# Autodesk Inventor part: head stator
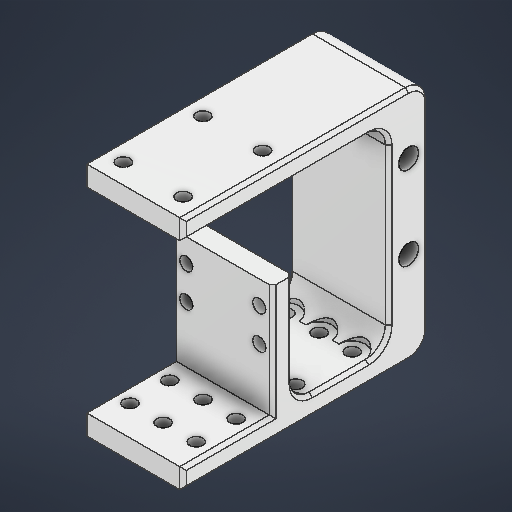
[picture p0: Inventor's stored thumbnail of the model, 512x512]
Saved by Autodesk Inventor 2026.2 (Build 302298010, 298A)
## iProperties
Created: 2026-04
Part Number: head stator
Material: ABS 플라스틱
Document SubType Name: Modeling
Designer: work
Density: 1.06 g/cm^3
Appearance: 매끄러움 - 흰색
Author: work
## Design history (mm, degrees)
sketch "스케치1"
  geometry: L1 (-12.5, 25)-(12.5, 25); L2 (12.5, 25)-(12.5, -25); L3 (12.5, -25)-(-12.5, -25); L4 (-12.5, -25)-(-12.5, 25); L5 (-12.5, 25)-(12.5, -25); L6 (12.5, 25)-(-12.5, -25); L7 (-24.5, 34)-(-0.5, 34); L8 (-0.5, 34)-(-0.5, 16); L9 (-0.5, 16)-(-24.5, 16); L10 (-24.5, 16)-(-24.5, 34); L11 (-24.5, 34)-(-0.5, 16); L12 (-0.5, 34)-(-24.5, 16); L13 (-18.5, -31)-(18.5, -31); L14 (18.5, -31)-(18.5, -19); L15 (18.5, -19)-(-18.5, -19); L16 (-18.5, -19)-(-18.5, -31); L17 (-18.5, -31)-(18.5, -19); L18 (18.5, -31)-(-18.5, -19); L19 (12.5, 25)-(24.5, 25); L20 (24.5, 43)-(30.5, 43); L21 (30.5, 43)-(30.5, -31); L22 (30.5, -31)-(24.5, -31); L23 (24.5, -31)-(24.5, 43); L24 (18.5, -19)-(24.5, -19); L25 (18.5, -31)-(24.5, -31); L26 (-18.5, 10)-(-24.5, 10); L27 (-24.5, 10)-(-24.5, -31); L28 (-24.5, -31)-(-18.5, -31); L29 (-18.5, -31)-(-18.5, 10); L30 (30.5, 37)-(24.5, 37); L31 (24.5, 37)-(24.5, 13); L32 (24.5, 13)-(30.5, 13); L33 (30.5, 13)-(30.5, 37); L34 (-6.5, 16)-(-18.5, 16); L35 (-18.5, 16)-(-18.5, 10); L36 (-18.5, 10)-(-6.5, 10); L37 (-6.5, 10)-(-6.5, 16); L38 (-0.5, 16)-(-24.5, 16); L39 (-24.5, 16)-(-24.5, 10); L40 (-24.5, 10)-(-0.5, 10); L41 (-0.5, 10)-(-0.5, 16); L42 (-18.5, -19)-(-34.5, -19); L43 (-34.5, -19)-(-34.5, -31); L44 (-34.5, -31)-(-18.5, -31); L45 (-18.5, -31)-(-18.5, -19); L46 (-34.5, -31)-(-40.5, -31); L47 (-40.5, -31)-(-40.5, 16); L48 (-40.5, 16)-(-34.5, 16); L49 (-34.5, 16)-(-34.5, -31); L50 (-34.5, 10)-(-24.5, 10); L51 (-24.5, 10)-(-24.5, 16); L52 (-24.5, 16)-(-34.5, 16); L53 (-34.5, 16)-(-34.5, 10); C1 r 4 at (12.5, 25); C2 r 3 at (12.5, -25); C3 r 3 at (-12.5, -25); 17 further points
  constraints: 106 end point, 23 parallel, 17 midpoint, 13 horizontal, 11 perpendicular, 5 point on line, 3 centre point, 3 coincident
  dimensions: "d0" = 25 distance of L2.end L3.end; "d1" = 50 distance of L1.end L2.end; "d2" = 8 diameter of C1; "d3" = 24 distance of L8.end L9.end; "d4" = 18 distance of L7.end L8.end; "d5" = 6 diameter of C2; "d6" = 6 diameter of C3; "d7" = 6 distance from line of L2.end L14; "d8" = 6 distance from line of L15 L2.end; "d9" = 12 distance of L19.end L19.start; "d11" = 24 distance from line of point (27.5, 13) L30; "d13" = 6 distance between parallel lines of L23 L21; "d14" = 6 distance between parallel lines of L30 L20; "d15" = 6 distance between parallel lines of L29 L27; "d17" = 6 distance of L34.end L35.end; "d18" = 12 distance from line of point (-18.5, 13) L37; "d19" = 6 distance between parallel lines of L39 L35; "d41" = 6 distance between parallel lines of L47 L49; "d42" = 10 distance between parallel lines of L53 L39
extrude "돌출1" new body sketch "스케치1" distance "d20" = 30; taper "d21" = 0 deg
sketch "스케치2"
  geometry: L1 (0, 74)-(0, 0) reference; L2 (0, 0)-(30, 0) reference; L3 (30, 74)-(30, 0) reference; L4 (0, 74)-(30, 74) reference; L5 (15, 0)-(15, 74); L6 (0, 37)-(30, 37); L7 (24, 30)-(6, 30); L8 (6, 30)-(6, 6); L9 (6, 6)-(24, 6); L10 (24, 6)-(24, 30); L11 (24, 30)-(6, 6); L12 (6, 30)-(24, 6); C1 r 2 at (6, 6); C2 r 2 at (24, 6); C3 r 2 at (24, 30); C4 r 2 at (6, 30); 2 further points
  constraints: 16 end point, 6 midpoint, 4 centre point, 4 coincident, 2 parallel, 1 horizontal, 1 perpendicular, 1 point on line
  dimensions: "d22" = 6 distance between parallel lines of L2 L9; "d23" = 24 distance of L7.end L8.end; "d24" = 18 distance of L8.end L9.end; "d25" = 4 diameter of C1; "d26" = 4 diameter of C2; "d27" = 4 diameter of C3; "d28" = 4 diameter of C4
extrude "돌출2" cut sketch "스케치2" stored distance "d29" = 36; taper "d30" = 0 deg
fillet "모깎기1" dims "d31" = 6
sketch "스케치4"
  geometry: L1 (30, 31)-(30, 25) reference; L2 (0, 31)-(0, 25) reference; L3 (0, 28)-(30, 28); L4 (26, 23)-(4, 23); L5 (4, 23)-(4, 33); L6 (4, 33)-(26, 33); L7 (26, 33)-(26, 23); L8 (26, 23)-(4, 33); L9 (4, 23)-(26, 33); C1 r 2 at (4, 23); C2 r 2 at (4, 33); C3 r 2 at (26, 33); C4 r 2 at (26, 23); 2 further points
  constraints: 14 end point, 5 midpoint, 4 centre point, 4 coincident, 2 parallel, 1 horizontal, 1 perpendicular
  dimensions: "d44" = 10 distance of L4.end L5.end; "d45" = 4 distance between parallel lines of L2 L5; "d46" = 4 diameter of C1; "d47" = 4 diameter of C2; "d48" = 4 diameter of C3; "d49" = 4 diameter of C4
extrude "돌출4" cut sketch "스케치4" distance "d50" = 30; taper "d51" = 0 deg
sketch "스케치5"
  geometry: L1 (16, -9.5)-(10, -9.5) reference; L2 (16, -0.5)-(16, -34.5) reference; L3 (10, -0.5)-(16, -0.5) reference; L4 (10, -28.5)-(10, -0.5) reference; L5 (-13, -34.5)-(4, -34.5) reference; L6 (-19, 18.5)-(-19, -28.5) reference; L7 (43, 24.5)-(-13, 24.5) reference; L8 (43, 30.5)-(43, 24.5) reference; L9 (-25, 30.5)-(43, 30.5) reference; L10 (-31, -34.5)-(-31, 24.5) reference; L11 (10, -40.5)-(-25, -40.5) reference; L12 (4, -34.5)-(43, -34.5); L13 (43, -34.5)-(43, -40.5); L14 (43, -40.5)-(4, -40.5); L15 (4, -40.5)-(4, -34.5); L16 (43, 30.5)-(43, 24.5) reference; C1 r 3 at (-25, 12.5) reference; C2 r 3 at (-25, -12.5) reference; A1 r 6 centre (10, -34.5) between (10, -40.5) and (16, -34.5) reference; A2 r 6 centre (4, -28.5) between (4, -34.5) and (10, -28.5) reference; A3 r 6 centre (-13, -28.5) between (-19, -28.5) and (-13, -34.5) reference; A4 r 6 centre (-13, 18.5) between (-13, 24.5) and (-19, 18.5) reference; A5 r 6 centre (-25, 24.5) between (-25, 30.5) and (-31, 24.5) reference; A6 r 6 centre (-25, -34.5) between (-31, -34.5) and (-25, -40.5) reference; 3 further points
  constraints: 8 end point, 2 parallel, 1 collinear, 1 horizontal, 1 perpendicular, 1 point on circle, 1 point on line
  dimensions: "d52" = 6 distance of L14.end L12.start
extrude "돌출5" join sketch "스케치5" stored distance "d53" = 10; taper "d54" = 0 deg
sketch "스케치6"
  geometry: L1 (0, 68)-(0, 0) reference; L2 (30, 0)-(0, 0) reference; L3 (30, 68)-(30, 0) reference; L4 (0, 68)-(30, 68) reference; L5 (25, 65)-(5, 65); L6 (5, 65)-(5, 5); L7 (5, 5)-(25, 5); L8 (25, 5)-(25, 65); L9 (0, 35)-(30, 35) reference; L10 (25, 65)-(5, 5); L11 (5, 65)-(25, 5); L12 (6, 35)-(2, 35) reference; L13 (6, 35)-(2, 35) reference; L14 (0, 35)-(0, 41) reference; L15 (0, 41)-(30, 41) reference; L16 (30, 35)-(30, 41) reference; L17 (0, 35)-(30, 35) reference; L18 (25, 47)-(5, 47); L19 (5, 47)-(5, 65); L20 (5, 65)-(25, 65); L21 (25, 65)-(25, 47); L22 (30, 6)-(0, 6) reference; L23 (25, 12)-(5, 12); L24 (5, 12)-(5, 29); L25 (5, 29)-(25, 29); L26 (25, 29)-(25, 12); L27 (25, 59)-(5, 59); L28 (15, 5)-(15, 65); 14 further points
  constraints: 32 end point, 9 midpoint, 9 point on line, 8 coincident, 6 parallel, 4 perpendicular, 3 horizontal
  dimensions: "d56" = 5 distance between parallel lines of L1 L6; "d57" = 5 distance between parallel lines of L2 L7; "d58" = 6 distance between parallel lines of L9 L25; "d59" = 6 distance between parallel lines of L22 L23; "d60" = 6 distance between parallel lines of L15 L18; "d61" = 6 distance between parallel lines of L5 L27
hole "구멍1" sketch "스케치6" at (25, 12), (25, 29), (25, 59), (25, 47), (5, 59), (5, 47), (5, 29), (5, 12), (15, 47), (15, 59), (15, 29), (15, 12) diameter "d62" = 4; stored, may be unused: countersink angle "d66" = 90 deg, drill point angle "d68" = 118 deg; dims "d63" = 6, "d64" = 6.2, "d65" = 3, "d67" = 6 (= d59)
chamfer "모따기1" distance "d69" = 1; stored, may be unused: second distance "d70" = 2, angle "d71" = 45 deg
sketch "스케치7"
  geometry: L1 (29, -39)-(29, 29) reference; L2 (1, -39)-(29, -39) reference; L3 (1, 29)-(1, -39) reference; L4 (29, 29)-(1, 29) reference; C1 r 2 at (15, 17) reference; C2 r 2 at (15, 0) reference; C3 r 2 at (15, -30) reference; C4 r 2 at (15, -18) reference; C5 r 2 at (5, 17) reference; C6 r 2 at (5, 0) reference; C7 r 2 at (5, -18) reference; C8 r 2 at (5, -30) reference; C9 r 2 at (25, -18) reference; C10 r 2 at (25, -30) reference; C11 r 2 at (25, 0) reference; C12 r 2 at (25, 17) reference; C13 r 4 at (25, 17); C14 r 4 at (25, 0); C15 r 4 at (15, 0); C16 r 4 at (15, 17); C17 r 4 at (5, 17); C18 r 4 at (5, 0); 1 further point
  constraints: 6 centre point, 1 coincident
  dimensions: "d72" = 8 diameter of C13; "d73" = 8 diameter of C14; "d74" = 8 diameter of C15; "d75" = 8 diameter of C16; "d76" = 8 diameter of C17; "d77" = 8 diameter of C18
extrude "돌출6" cut sketch "스케치7" distance "d78" = 10; taper "d79" = 0 deg
chamfer "모따기2" distance "d80" = 1; stored, may be unused: second distance "d81" = 2, angle "d82" = 45 deg
feature "е耀з耀й耀л耀н耀п耀с耀у耀" dims "d0" = 25, "d1" = 50, "d2" = 8, "d3" = 24, "d4" = 18, "d5" = 6, "d6" = 6, "d7" = 6, "d8" = 6, "d9" = 12, "d11" = 24, "d13" = 6, "d14" = 6, "d15" = 6, "d17" = 6, "d18" = 12, "d19" = 6, "d20" = 30, "d21" = 0, "d22" = 6, "d23" = 24, "d24" = 18, "d25" = 4, "d26" = 4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
node "솔리드1"
node "투영된 루프1"
node "투영된 루프3"
node "투영된 루프4"
node "투영된 루프5"
node "투영된 루프6"
node "투영된 루프7"
feature "A9D066F2-1C7D-4E18-AEED-F7BC21143FA4" dims "d62" = 4, "d63" = 6, "d64" = 6.2, "d65" = 3, "d66" = 90 deg, "d67" = 6 (= d59), "d68" = 118 deg
